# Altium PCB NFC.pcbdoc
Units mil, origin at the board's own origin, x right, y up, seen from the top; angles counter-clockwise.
Board outline 4070 x 3225 mil, 2 copper layers (Top Layer, Bottom Layer); 55 components, 46 nets, 197 pads, 132 vias.
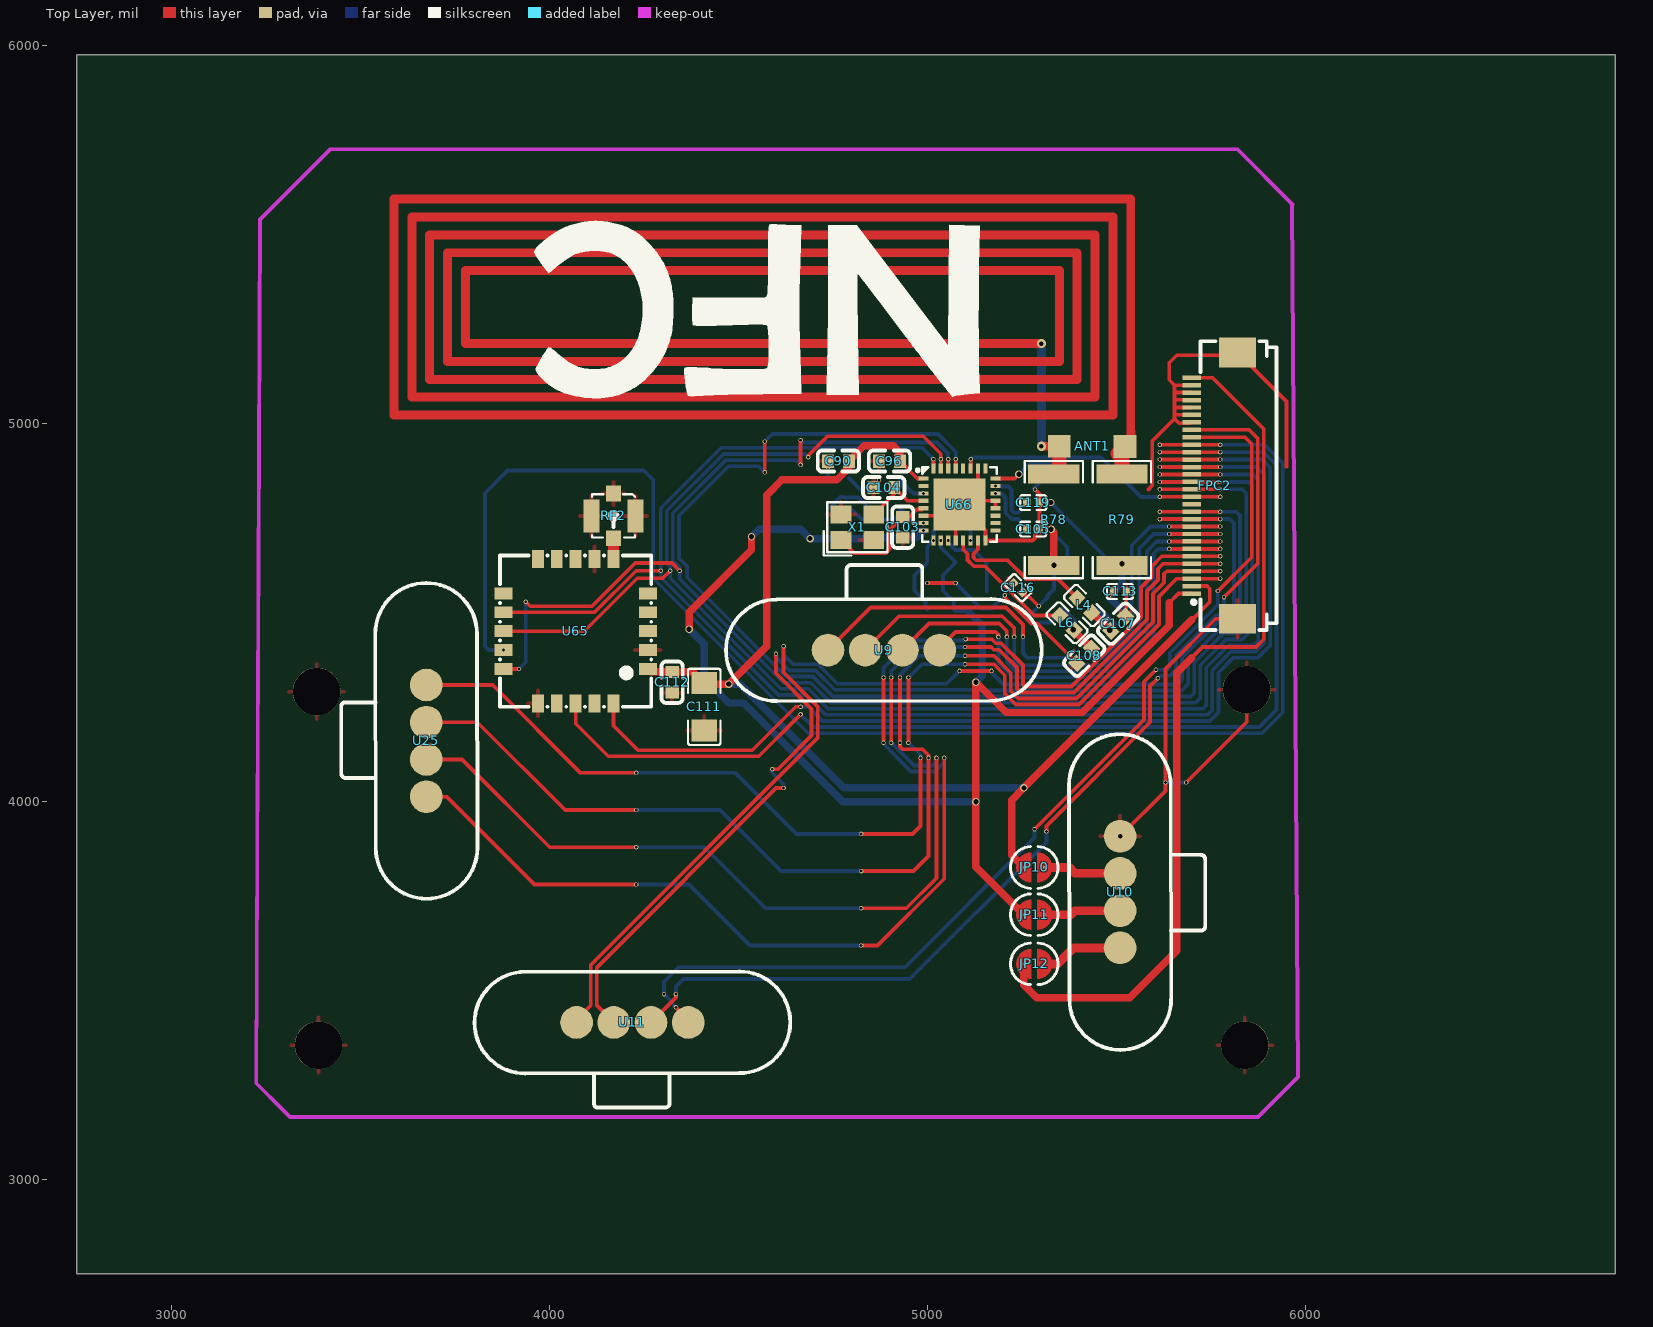
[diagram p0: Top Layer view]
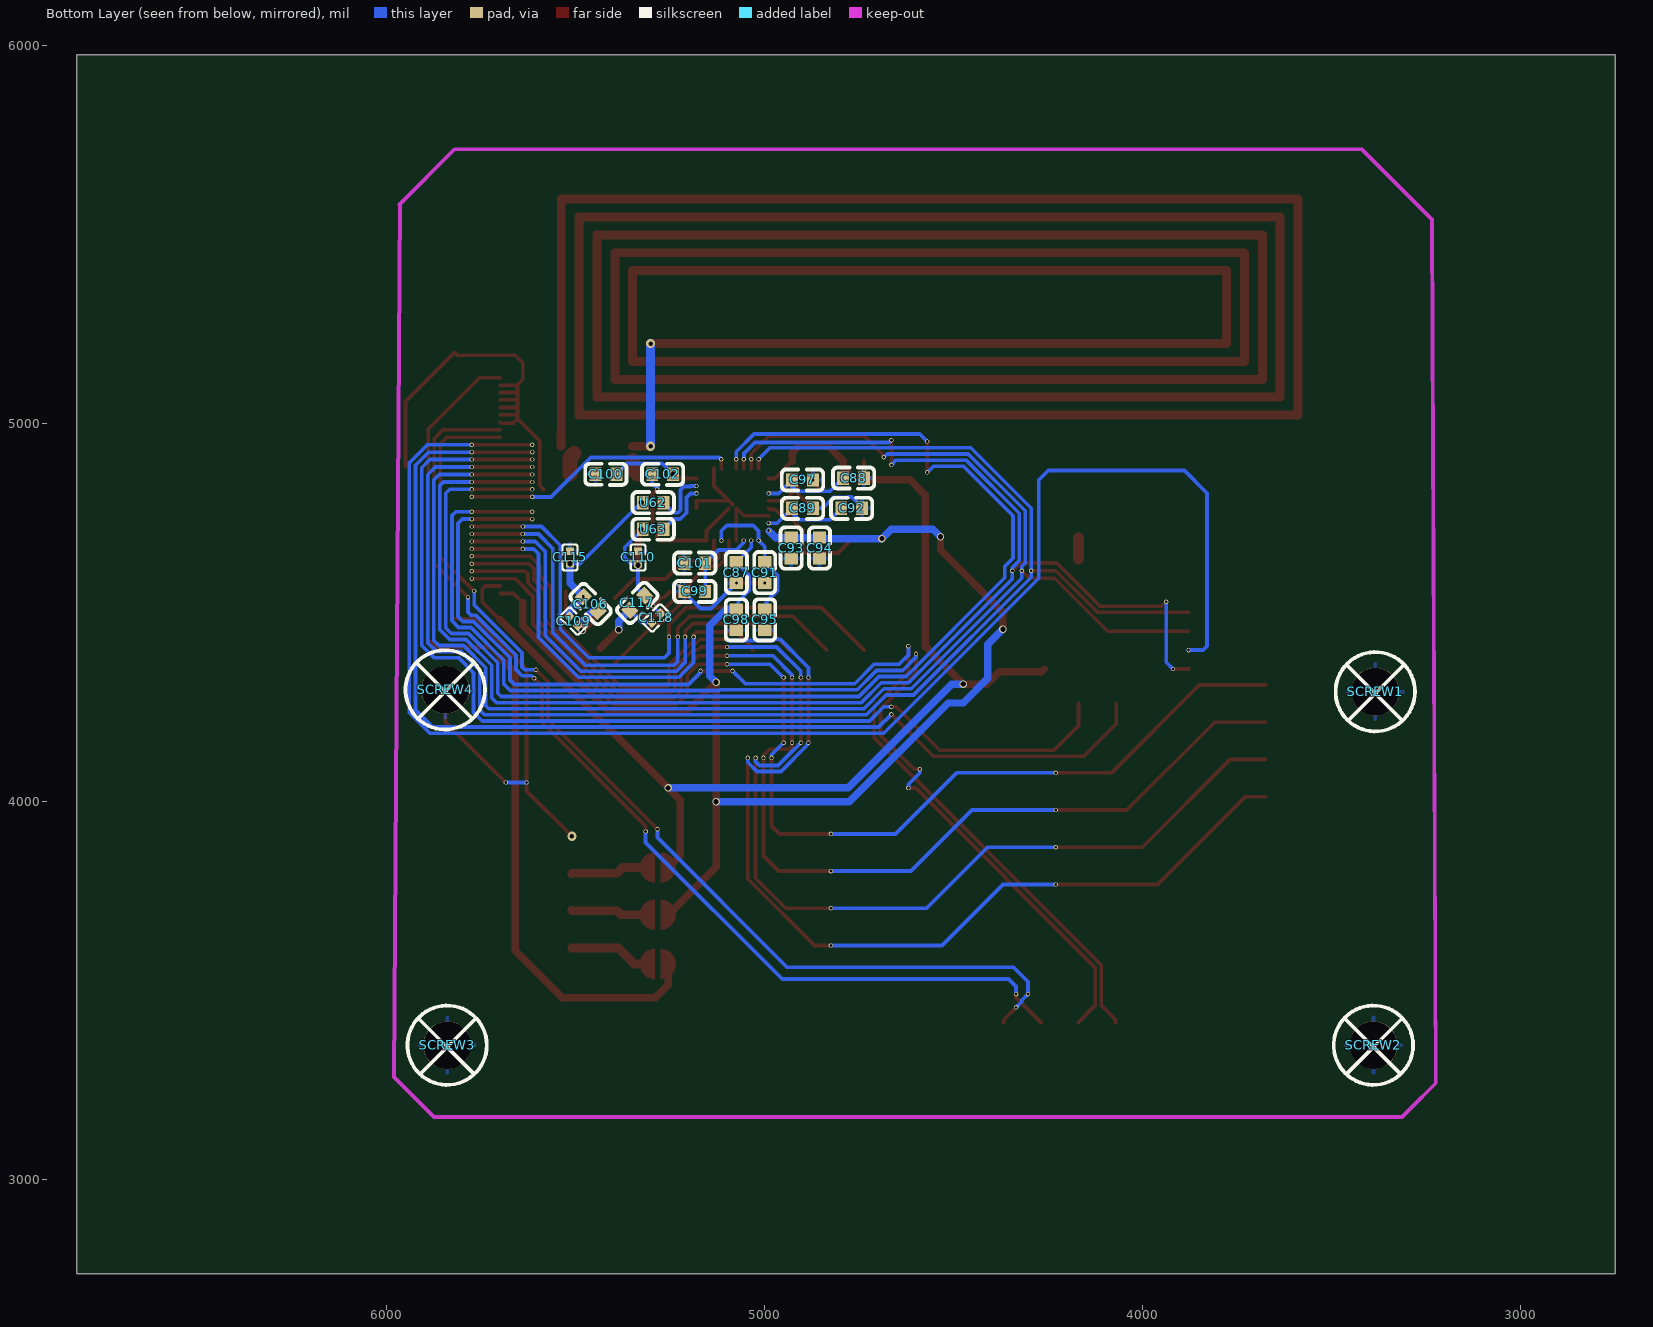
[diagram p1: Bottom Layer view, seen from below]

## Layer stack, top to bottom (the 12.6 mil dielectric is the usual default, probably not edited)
Top Layer: signal copper (thickness not stored)
Dielectric: dielectric 12.6, FR-4, Dk 4.8
Bottom Layer: signal copper (thickness not stored)

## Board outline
6820,2750 2750,2750 2750,5975 6820,5975

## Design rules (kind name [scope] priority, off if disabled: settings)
BoardOutlineClearance copperThickness1oz [All] p0: genericclearance=10 ignorepadtopadclearanceinfootprint=FALSE except(0: Arc-SplitContinuation Track-SplitContinuation SMDPad-SplitContinuation THPad-SplitContinuation Via-SplitContinuation Fill-SplitContinuation Poly-SplitContinuation Region-SplitContinuation Text-SplitContinuation; 6: Track-CutoutEdge SMDPad-CutoutEdge THPad-CutoutEdge Via-CutoutEdge Region-CutoutEdge; 11.8: Track-OutlineEdge SMDPad-OutlineEdge THPad-OutlineEdge Via-OutlineEdge Fill-OutlineEdge Region-OutlineEdge Poly-OutlineEdge Text-OutlineEdge Fill-CutoutEdge)
BoardOutlineClearance copperThickness2oz [All] p0: genericclearance=10 ignorepadtopadclearanceinfootprint=FALSE except(0: Arc-SplitContinuation Track-SplitContinuation SMDPad-SplitContinuation THPad-SplitContinuation Via-SplitContinuation Fill-SplitContinuation Poly-SplitContinuation Region-SplitContinuation Text-SplitContinuation; 6: Track-CutoutEdge SMDPad-CutoutEdge THPad-CutoutEdge Via-CutoutEdge Region-CutoutEdge; 11.8: Track-OutlineEdge SMDPad-OutlineEdge THPad-OutlineEdge Via-OutlineEdge Fill-OutlineEdge Region-OutlineEdge Poly-OutlineEdge Text-OutlineEdge Fill-CutoutEdge)
Clearance copperThickness1oz [(InNet('ESP_MISO') OR InNet('ESP_SCK') OR InNet('ESP_CS') OR InNet('ESP_MOSI') OR InNet('+5V') OR InNet('3V3_VDD') OR InNet('1V8_VDD') OR InNet('CS3') OR InNet('CS4') OR InNet('ESP_SDA') OR InNet('TXD0') OR InNet('RXD0') OR InNet('$3N153') OR InNet('CC_CSN') OR InNet('$3N151') OR InNet('ESP_SCL') OR InNet('NFC_IRQ') OR InNet('NFC_CS') OR InNet('CC_SCK') OR InNet('CC_MOSI') OR InNet('CC_MISO') OR InNet('CC_GDO2') OR InNet('CC_GDO0') OR InNet('$3N131') OR InNet('RFO2') OR InNet('RFO1') OR InNet('CS1') OR InNet('CS2') OR InNet('$3N159') OR InNet('$3N158') OR InNet('$3N160') OR InNet('$3N4436') OR InNet('$3N4438') OR InNet('$3N4437') OR InNet('RFI2') OR InNet('RFI1') OR InNet('$3N119') OR InNet('VDD_A') OR InNet('$3N123') OR InNet('AM') OR InNet('$3N154') OR InNet('GND') OR InNet('ANT1_1') OR InNet('XTO') OR InNet('XTI') OR InNet('$3N136'))] p1: gap=7 ignorepadtopadclearanceinfootprint=FALSE except(4: Track-Track; 6: Track-SMDPad SMDPad-SMDPad Track-THPad SMDPad-THPad THPad-THPad Track-Via SMDPad-Via THPad-Via Via-Via SMDPad-Fill THPad-Fill Via-Fill Fill-Fill Track-Region SMDPad-Region THPad-Region Via-Region Region-Region Track-Poly SMDPad-Poly THPad-Poly Via-Poly Fill-Poly Region-Poly Poly-Poly Track-Text SMDPad-Text THPad-Text Via-Text Fill-Text Region-Text Poly-Text Text-Text; 6.9: Track-Hole SMDPad-Hole THPad-Hole Via-Hole Fill-Hole Region-Hole Poly-Hole Text-Hole Sheet-Hole; 11.8: Track-Fill Fill-Region Track-Sheet SMDPad-Sheet THPad-Sheet Via-Sheet Fill-Sheet Region-Sheet Poly-Sheet Text-Sheet)
Clearance copperThickness2oz [All] p1: gap=7 ignorepadtopadclearanceinfootprint=FALSE except(6: Track-SMDPad SMDPad-SMDPad Track-THPad SMDPad-THPad THPad-THPad Track-Via SMDPad-Via THPad-Via Via-Via SMDPad-Fill THPad-Fill Via-Fill Fill-Fill Track-Region SMDPad-Region THPad-Region Via-Region Region-Region Track-Poly SMDPad-Poly THPad-Poly Via-Poly Fill-Poly Region-Poly Poly-Poly Track-Text SMDPad-Text THPad-Text Via-Text Fill-Text Region-Text Poly-Text Text-Text; 6.9: Track-Hole SMDPad-Hole THPad-Hole Via-Hole Fill-Hole Region-Hole Poly-Hole Text-Hole Sheet-Hole; 8: Track-Track; 11.8: Track-Fill Fill-Region Track-Sheet SMDPad-Sheet THPad-Sheet Via-Sheet Fill-Sheet Region-Sheet Poly-Sheet Text-Sheet)
DiffPairsRouting differentialPair [All] p1: maxuncoupledlength=10 minlimit=6 maxlimit=6 mostfreqgap=6 toplayer_minwidth=5 toplayer_prefwidth=10 toplayer_maxwidth=100 bottomlayer_minwidth=5 bottomlayer_prefwidth=10 bottomlayer_maxwidth=100
PasteMaskExpansion pasteMaskExpansion [All] p1: expansion=0
PlaneConnect innerPlane [All] p1: planeconnectstyle=Relief reliefexpansion=20 reliefentries=4 reliefconductorwidth=10 reliefairgap=10
PolygonConnect copperRegion [All] p1: connectstyle=Relief reliefentries=4 reliefconductorwidth=10 polygonreliefangle="90 Angle" airgapwidth=10
RoutingVias viaSize [All] p1: viastyle="Through Hole" holewidth=7.5 minholewidth=7.5 maxholewidth=248.0314 width=11.4 minwidth=11.4 maxwidth=300
SolderMaskExpansion solderMaskExpansion [All] p1: useseparateexpansions=TRUE expansion=2 expansionbottom=2
Width copperThickness1oz [All] p1: maxlimit=100 minlimit=5 preferedwidth=10
Width copperThickness2oz [All] p1: maxlimit=100 minlimit=8 preferedwidth=10

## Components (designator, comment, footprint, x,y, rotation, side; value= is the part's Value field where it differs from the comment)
ANT1 "NFC_13.56" "NFC ANTENNA" 5550,5010 r180 top
C87 "10nF" C0603 5075,4605 r90 bottom
C88 "2.2uF" C0603 4765,4855 r180 bottom
C89 "10nF" C0603 4900,4775 r180 bottom
C90 "2.2uF" C0603 4765,4900 r180 top
C91 "10nF" C0603 5000,4605 r90 bottom
C92 "2.2uF" C0603 4770,4775 r0 bottom
C93 "10nF" C0603 4930,4670 r90 bottom
C94 "2.2uF" C0603 4855,4670 r90 bottom
C95 "2.2uF" C0603 5000,4480 r90 bottom
C96 "10nF" C0603 4900,4900 r180 top
C97 "10nF" C0603 4900,4850 r180 bottom
C98 "2.2uF" C0603 5075,4480 r90 bottom
C99 "2.2uF" C0603 5185,4555 r180 bottom
C100 "1uF" C0603 5420,4865 r0 bottom
C101 "10nF" C0603 5185,4630 r180 bottom
C102 "10nF" C0603 5270,4865 r180 bottom
C103 "6pF" C0603 4935,4725 r90 top
C104 "6pF" C0603 4885,4830 r0 top
C105 "220pF" C0402 5280,4720 r0 top
C106 "82pF" C0603 5460.43,4521.89 r45 bottom
C107 "680pF" C0603 5505,4470 r45 top
C108 "680pF" C0603 5415,4385 r45 top
C109 "4pF" C0402 5505.43,4476.89 r225 bottom
C110 "110pF" C0402 5335,4645 r270 bottom
C111 "10uF" C1206 4410,4250 r90 top
C112 "100nF" C0603 4325,4315 r270 top
C113 "4pF" C0402 5510,4555 r0 top
C115 "110pF" C0402 5515,4645 r90 bottom
C116 "4pF" C0402 5240,4565 r315 top
C117 "82pF" C0603 5337.2,4524.96 r135 bottom
C118 "4pF" C0402 5287.2,4484.96 r315 bottom
C119 "220pF" C0402 5280,4790 r0 top
FPC2 "FPC-05F-30PH20" FPC-SMD_30P-P0.50_XUNPU_FPC-05F-30PH20 5760,4835 r90 top
JP10 "2P Solder UNBridge Jumper" "SOLDER BRIDGE 2P UNBRIDGED" 5285,3825 r180 top
JP11 "2P Solder UNBridge Jumper" "SOLDER BRIDGE 2P UNBRIDGED" 5285,3700 r180 top
JP12 "2P Solder UNBridge Jumper" "SOLDER BRIDGE 2P UNBRIDGED" 5285,3570 r180 top
L4 "270nH" L0603 5415.47,4518 r315 top
L6 "270nH" L0603 5369.51,4472.04 r315 top
R78 "2Ω" R2512 5335,4745 r90 top
R79 "2Ω" R2512 5515,4745 r90 top
RF2 "HC-RF-IPEX0303-01" IPEX-SMD_HC-RF-IPEX0303-01 4170,4755 r0 top
SCREW1 "Screw-M3" SCREW-M3 3385,4290 r180 bottom
SCREW2 "Screw-M3" SCREW-M3 3390,3355 r180 bottom
SCREW3 "Screw-M3" SCREW-M3 5840,3355 r180 bottom
SCREW4 "Screw-M3" SCREW-M3 5845,4295 r180 bottom
U9 "YZ92015035T-04025-01" CONN-SMD_4P-P2.50_YZ92015035T-04025-01 4885,4400 r180 top
U10 "YZ92015035T-04025-01" CONN-SMD_4P-P2.50_YZ92015035T-04025-01 5510,3760 r90 top
U11 "YZ92015035T-04025-01" CONN-SMD_4P-P2.50_YZ92015035T-04025-01 4220,3415 r0 top
U25 "YZ92015035T-04025-01" CONN-SMD_4P-P2.50_YZ92015035T-04025-01 3675,4160 r270 top
U62 "10pF" C0603 5295,4790 r0 bottom
U63 "10pF" C0603 5295,4719.65 r0 bottom
U65 "E07-400MM10S" COMM-SMD_E07-400MM10S 4070,4450 r180 top
U66 "ST25R3916B-AQWT" VFQFPN-32_L5.0-W5.0-P0.50-TL-EP3.5 5085,4785 r0 top
X1 "27.12MHz" CRYSTAL-SMD_4P-L3.2-W2.5-BL 4815,4725 r0 top

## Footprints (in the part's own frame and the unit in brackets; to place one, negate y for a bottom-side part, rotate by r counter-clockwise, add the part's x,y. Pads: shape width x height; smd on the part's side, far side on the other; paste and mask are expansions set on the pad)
C0402 [mm]
  rect 0.5x0.54 smd: 1(-0.42,0) 2(0.42,0)
  silkscreen extent -0.87,-0.5 0.87,0.5
C0603 [mm]
  rect 0.8x0.9 smd: 1(-0.7,0) 2(0.7,0)
  silkscreen extent -1.39,-0.71 1.39,0.71
C1206 [mm]
  rect 1.485x1.728 smd: 1(-1.593,0) 2(1.593,0)
  silkscreen extent -2.56,-1.09 2.56,1.09
COMM-SMD_E07-400MM10S [mm]
  rect 1.2x0.8 smd: 1(-4.85,2.54) 2(-4.85,1.27) 3(-4.85,0) 4(-4.85,-1.27) 5(-4.85,-2.54) 11(4.85,-2.54) 12(4.85,-1.27) 13(4.85,0) 14(4.85,1.27) 15(4.85,2.54)
  rect 0.8x1.2 smd: 6(-2.54,-4.85) 7(-1.27,-4.85) 8(0,-4.85) 9(1.27,-4.85) 10(2.54,-4.85) 16(2.54,4.85) 17(1.27,4.85) 18(0,4.85) 19(-1.27,4.85) 20(-2.54,4.85)
  silkscreen extent -5.08,-5.08 5.08,5.08
CONN-SMD_4P-P2.50_YZ92015035T-04025-01 [mm]
  round 2.2 smd: 1(-3.75,0) 2(-1.25,0) 3(1.25,0) 4(3.75,0)
  silkscreen extent -10.61,-5.72 10.61,3.43
CRYSTAL-SMD_4P-L3.2-W2.5-BL [mm]
  rect 1.4x1.2 smd: 1(-1.1,-0.85) 2(1.1,-0.85) 3(1.1,0.85) 4(-1.1,0.85)
  silkscreen extent -2.26,-1.91 2.03,1.68
FPC-SMD_30P-P0.50_XUNPU_FPC-05F-30PH20 [mm]
  rect 0.3x1.25 smd: 1(-7.25,1.537) 2(-6.75,1.537) 3(-6.25,1.537) 4(-5.75,1.537) 5(-5.25,1.537) 6(-4.75,1.537) 7(-4.25,1.537) 8(-3.75,1.537) 9(-3.25,1.537) 10(-2.75,1.537) 11(-2.25,1.537) 12(-1.75,1.537) 13(-1.25,1.537) 14(-0.75,1.537) 15(-0.25,1.537) 16(0.25,1.537) 17(0.75,1.537) 18(1.25,1.537) 19(1.75,1.537) 20(2.25,1.537) 21(2.75,1.537) 22(3.25,1.537) 23(3.75,1.537) 24(4.25,1.537) 25(4.75,1.537) 26(5.25,1.537) 27(5.75,1.537) 28(6.25,1.537) 29(6.75,1.537) 30(7.25,1.537)
  rect 2x2.5 smd: 31(8.94,-1.537) 32(-8.94,-1.537)
  silkscreen extent -9.7,-4.15 9.7,1.53
IPEX-SMD_HC-RF-IPEX0303-01 [mm]
  rect 1x1.05 smd: 1(0,-1.5) 4(0,1.5)
  rect 1.05x2.2 smd: 2(1.475,0) 3(-1.475,0)
  silkscreen extent -1.45,-1.45 1.45,1.45
L0603 [mm]
  rect 0.8x0.864 smd: 1(-0.7,0) 2(0.7,0)
  silkscreen extent -1.42,-0.65 1.42,0.65
"NFC ANTENNA" [mil]
  rect 60x60 smd: 1(27.16,71.65) 2(200.79,70.87)
  Top Layer lines w23.62: 248.03,70.87 245.27,70.87 200.79,70.87 ; 248.03,-200.79 1771.66,-200.79 1771.66,-393.7 200.79,-393.7 200.79,-153.54 1818.9,-153.54 1818.9,-440.94 153.54,-440.94 153.54,-106.3 1866.14,-106.3 1866.14,-488.19 106.3,-488.19 106.3,-59.06 1913.38,-59.06 1913.38,-535.43 59.1,-535.4 59.1,-11.8 ; 59.06,-11.81 1960.63,-11.81 1960.63,-582.68 11.81,-582.68 11.81,-11.81 11.42,70.87
  Bottom Layer lines w23.62: 248.03,70.87 248.03,-200.79
  silkscreen extent 411,-525 1590,-56
R2512 [mil]
  rect 50.49x136.06 smd: 1(-120.72,0) 2(120.72,0)
  silkscreen extent -155,-77 155,77
SCREW-M3 [mil]
  round 126 hole 126: 1(0,0)
  silkscreen extent -105,-105 105,105
"SOLDER BRIDGE 2P UNBRIDGED" [mm]
  round 0.2 smd: 1(-0.65,0) 2(0.75,0)
  Top Layer region: 0.25,-1 0.296,-0.999 0.342,-0.996 0.388,-0.99 0.434,-0.983 0.479,-0.973 0.524,-0.962 0.568,-0.948 0.611,-0.932 0.654,-0.915 0.696,-0.895 0.737,-0.874 0.776,-0.85 0.815,-0.825 0.853,-0.798 0.889,-0.769 0.924,-0.739 0.957,-0.707 0.989,-0.674 1.019,-0.639 1.048,-0.603 1.075,-0.565 1.1,-0.526 1.124,-0.487 1.145,-0.446 1.165,-0.404 1.182,-0.361 1.198,-0.318 1.212,-0.274 1.223,-0.229 1.233,-0.184 1.24,-0.138 1.246,-0.092 1.249,-0.046 1.25,0 1.249,0.046 1.246,0.092 1.24,0.138 1.233,0.184 1.223,0.229 1.212,0.274 1.198,0.318 1.182,0.361 1.165,0.404 1.145,0.446 1.124,0.487 1.1,0.526 1.075,0.565 1.048,0.603 1.019,0.639 0.989,0.674 0.957,0.707 0.924,0.739 0.889,0.769 0.853,0.798 0.815,0.825 0.776,0.85 0.737,0.874 0.696,0.895 0.654,0.915 0.611,0.932 0.568,0.948 0.524,0.962 0.479,0.973 0.434,0.983 0.388,0.99 0.342,0.996 0.296,0.999 0.25,1
  Top Layer region: -0.15,-1 -0.196,-0.999 -0.242,-0.996 -0.288,-0.99 -0.334,-0.983 -0.379,-0.973 -0.424,-0.962 -0.468,-0.948 -0.511,-0.932 -0.554,-0.915 -0.596,-0.895 -0.637,-0.874 -0.676,-0.85 -0.715,-0.825 -0.753,-0.798 -0.789,-0.769 -0.824,-0.739 -0.857,-0.707 -0.889,-0.674 -0.919,-0.639 -0.948,-0.603 -0.975,-0.565 -1,-0.526 -1.024,-0.487 -1.045,-0.446 -1.065,-0.404 -1.082,-0.361 -1.098,-0.318 -1.112,-0.274 -1.123,-0.229 -1.133,-0.184 -1.14,-0.138 -1.146,-0.092 -1.149,-0.046 -1.15,0 -1.149,0.046 -1.146,0.092 -1.14,0.138 -1.133,0.184 -1.123,0.229 -1.112,0.274 -1.098,0.318 -1.082,0.361 -1.065,0.404 -1.045,0.446 -1.024,0.487 -1,0.526 -0.975,0.565 -0.948,0.603 -0.919,0.639 -0.889,0.674 -0.857,0.707 -0.824,0.739 -0.789,0.769 -0.753,0.798 -0.715,0.825 -0.676,0.85 -0.637,0.874 -0.596,0.895 -0.554,0.915 -0.511,0.932 -0.468,0.948 -0.424,0.962 -0.379,0.973 -0.334,0.983 -0.288,0.99 -0.242,0.996 -0.196,0.999 -0.15,1
  silkscreen extent -1.55,-1.4 1.65,1.4
VFQFPN-32_L5.0-W5.0-P0.50-TL-EP3.5 [mm]
  rect 0.665x0.28 smd: 1(-2.42,1.75) 2(-2.42,1.25) 3(-2.42,0.75) 4(-2.42,0.25) 5(-2.42,-0.25) 6(-2.42,-0.75) 7(-2.42,-1.25) 8(-2.42,-1.75) 17(2.42,-1.75) 18(2.42,-1.25) 19(2.42,-0.75) 20(2.42,-0.25) 21(2.42,0.25) 22(2.42,0.75) 23(2.42,1.25) 24(2.42,1.75)
  rect 0.28x0.665 smd: 9(-1.75,-2.42) 10(-1.249,-2.42) 11(-0.75,-2.42) 12(-0.249,-2.42) 13(0.25,-2.42) 14(0.751,-2.42) 15(1.25,-2.42) 16(1.751,-2.42) 25(1.751,2.42) 26(1.25,2.42) 27(0.751,2.42) 28(0.25,2.42) 29(-0.249,2.42) 30(-0.75,2.42) 31(-1.249,2.42) 32(-1.75,2.42)
  rect 3.5x3.5 smd: 33(0,0)
  silkscreen extent -2.9,-2.5 2.5,2.5

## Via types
v1: diameter 11.42, hole 7.48, Top Layer to Bottom Layer, 102 vias
v2: diameter 19.68, hole 13.78, Top Layer to Bottom Layer, 14 vias
v3: diameter 11.4, hole 7.5, Top Layer to Bottom Layer, 13 vias
v4: diameter 24, hole 12, Top Layer to Bottom Layer, 2 vias
v5: diameter 24.41, hole 12.2, Top Layer to Bottom Layer, 1 vias

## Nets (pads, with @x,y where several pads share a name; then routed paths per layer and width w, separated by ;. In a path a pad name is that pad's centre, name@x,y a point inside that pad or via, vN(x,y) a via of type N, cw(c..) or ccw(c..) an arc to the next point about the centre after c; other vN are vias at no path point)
1V8_VDD: FPC2.30 JP12.2 | length 2330.7
  Top Layer w10: FPC2.30 5754.57,5120.43 5890,4985 5890,4428.79 5869.14,4407.93 5727.93,4407.93 5700,4380
  Top Layer w19.68: JP12.2 5255.47,3514.53 5290,3480 5535,3480 5660,3605 5660,4340 5700,4380
3V3_VDD: C90.1 C96.1 C111.2 C112.1 FPC2.2 JP10.2 U65.1 U66.1 | length 3212
  Top Layer w10: C96.1 4973.66,4853.9 U66.1 ; FPC2.2 5740,4569.25 5747.07,4562.18 5747.07,4527.07 5700,4480
  Top Layer w19.68: U65.1 4268.37,4342.56 C112.1 4380.14,4342.56 C111.2 4412.7,4310 v2(4475,4310) 4575,4410 4575,4810 4615,4850 4760,4850 4792.56,4882.56 C90.1 4832.56,4940 4910,4940 4927.56,4922.44 C96.1 ; JP10.2 5223.12,3857.35 5223.12,4003.12 v2(5255.47,4035.47) 5700,4480
  Bottom Layer w19.68: v2(4475,4310) 4505,4310 4779.53,4035.47 v2(5255.47,4035.47)
$3N119: C88.1 C97.1 U66.3 | length 249
  Bottom Layer w10: C88.1 4827.56,4820 4915,4820 4927.56,4832.56 C97.1 4963.04,4814.52 v1(4989.73,4814.52)
$3N123: C91.2 C95.2 U66.9 U66.14 | length 378.3
  Bottom Layer w10: C95.2 4995,4512.56 4995,4528.44 4966.3,4557.14 4966.3,4597.74 4995,4626.44 4995,4627.56 C91.2 5000,4673.61 v1(5016.12,4689.72) 5016.12,4715 5030.56,4729.44 5100.56,4729.44 5115,4715 5115,4690.17 v1(5114.55,4689.72)
$3N131: C100.1 C102.2 U66.24 | length 240.5
  Top Layer w10: U66.24 5231.33,4853.89 v2(5242.44,4865)
  Bottom Layer w10: v2(5242.44,4865) 5271.14,4893.7 5363.74,4893.7 C100.1
$3N136: RF2.1 U65.6 | length 55
  Top Layer w30: U65.6 RF2.1
$3N151: C106.1 C107.1 C109.2 L4.2 | length 152
  Top Layer w19.68: L4.2 5436.94,4498.52 v2(5482.73,4452.73)
  Bottom Layer w19.68: C106.1 5456.53,4502.4 C109.2 5493.73,4463.73 v2(5482.73,4452.73)
$3N153: C108.2 C117.1 C118.2 L6.2 | length 204.3
  Top Layer w19.68: v2(5385.93,4453.72) 5385.93,4453.05 C108.2
  Bottom Layer w10: C118.2 5324.48,4473.27 C117.1
  Bottom Layer w19.68: C117.1 5385.93,4476.23 v2(5385.93,4453.72)
$3N154: C106.2 C109.1 C113.1 C115.1 R79.1 U62.2 | length 444.5
  Top Layer w10: v3(5479.92,4541.38) C113.1@5493.46,4554.92
  Bottom Layer w10: v2(5326.49,4790.35) 5488.39,4628.46 v2(5515,4628.46)
  Bottom Layer w19.68: v2(5515,4628.46) 5515,4576.46 v3(5479.92,4541.38) 5517.12,4504.17 C109.1
$3N158: ANT1.1 R79.2 | length 58.7
  Top Layer w39.37: ANT1.1@5504.6,4920.11 5515,4909.71 R79.2
$3N159: ANT1.2 R78.2 | length 41.8
  Top Layer w39.37: R78.2 5349.21,4879.93 5349.21,4901.65
$3N160: C110.2 C116.2 C117.2 C118.1 R78.1 U63.2 | length 449.8
  Top Layer w10: C116.2 5265,4540 5271.23,4540 v3(5295.04,4516.19)
  Top Layer w19.68: v2(5327.56,4719.65) 5335,4712.21 v2(5335,4624.28)
  Bottom Layer w10: C118.1 v3(5295.04,4516.19) 5317.71,4538.86 C117.2 5335,4561.74 C110.2 5353.46,4628.46 5370,4645 5370,4672.21 U63.2
$3N4436: JP12.1 U10.1 | length 217
  Top Layer w23.62: JP12.1 5345,3570 5387.4,3612.4 U10.1
$3N4437: JP11.1 U10.2 | length 203.5
  Top Layer w23.62: JP11.1 5380,3700 5390,3710 U10.2
$3N4438: JP10.1 U10.3 | length 205.6
  Top Layer w23.62: JP10.1 5375,3825 5390,3810 U10.3
+5V: C87.2 C93.2 C94.2 C98.2 FPC2.1 JP11.2 U66.8 U66.10 | length 3700.9
  Top Layer w10: 5640,4525 5664.57,4549.57 FPC2.1
  Top Layer w19.68: v2(4370,4455) 4370,4500 4535,4665 v2(4535,4700) ; JP11.2 5128.58,3826.89 v2(5128.58,3998.69) v2(5128.58,4315) 5128.83,4315 5208.83,4235 5410,4235 5640,4465 5640,4525
  Bottom Layer w10: v1(5035.81,4689.72) 5035.81,4671.75 C87.2 5070,4627.56 5070,4626.44 5041.3,4597.74 5041.3,4557.14 5070,4528.44 5070,4512.56 C98.2
  Bottom Layer w19.68: v2(4370,4455) 4410,4415 4410,4325 4475,4260 4515,4260 4776.31,3998.69 v2(5128.58,3998.69) ; v2(4535,4700) 4555,4720 4665,4720 v2(4690,4695) 4852.44,4695 C94.2 C93.2 4971.2,4697.56 v1@4987.88,4714.24 ; C98.2 5102.44,4507.56 5145,4465 5145,4331.42 v2(5128.58,4315)
  other v1: 4989.73,4716.09
AM: C99.2 C101.2 U66.11 | length 204.7
  Bottom Layer w10: v1(5055.49,4689.72) 5055.49,4684.51 5075,4665 5122.44,4665 C101.2 C99.2
ANT1_1: 
  other v4: 5301.97,4939.13 5301.97,5210.79
CC_CSN: FPC2.21 U65.14 | length 4061
  Top Layer w10: v1(5615,4943.27) FPC2.21 v1(5775,4943.27)
  Bottom Layer w10: v1@3879.05,4400 3840,4400 3830,4410 3830,4815 3890,4875 4250,4875 4275,4850 4275,4590 4685,4180 5885,4180 5940,4235 5940,4895 5891.73,4943.27 v1(5775,4943.27)
  other v1: 3879.06,4399.99
CC_GDO0: FPC2.20 U65.18 | length 2992.5
  Top Layer w10: U65.18 4070,4205 4155.98,4119.02 4554.02,4119.02 v1(4665,4230) ; v1(5615,4923.58) FPC2.20 v1(5775,4923.58)
  Bottom Layer w10: v1(4665,4230) 4698.7,4196.3 5878.7,4196.3 5923.7,4241.3 5923.7,4888.7 5888.81,4923.58 v1(5775,4923.58)
CC_GDO2: FPC2.19 U65.20 | length 2802.3
  Top Layer w10: U65.20 4170,4200 4235,4135 4537.16,4135 4652.16,4250 v1(4665,4250) ; v1(5615,4903.9) FPC2.19 v1(5775,4903.9)
  Bottom Layer w10: v1(4665,4250) 4685,4250 4722.71,4212.29 5747.29,4212.29 5770,4235 5770,4340 5810,4380 5875,4380 5907.39,4412.39 5907.39,4882.39 5885.89,4903.9 v1(5775,4903.9)
CC_MISO: FPC2.18 U65.12 U66.32 | length 4085.4
  Top Layer w10: U65.12 4119.99,4499.99 4230,4610 v1(4295,4610) ; U66.32 v1(5016.12,4905) ; v1(5615,4884.21) FPC2.18 v1(5775,4884.21)
  Bottom Layer w10: v1(5016.12,4905) 4986.12,4935 4455,4935 4295,4775 v1(4295,4610) 4295,4592.61 4606.3,4281.3 4678.7,4281.3 4731.2,4228.8 5741.2,4228.8 5754.02,4241.62 5754.02,4346.62 5803.38,4395.98 5868.38,4395.98 5891.41,4419.02 5891.41,4863.59 5870.79,4884.21 v1(5775,4884.21)
CC_MOSI: FPC2.17 U65.13 U66.31 | length 4087.1
  Top Layer w10: U65.13 4092.6,4449.99 4232.61,4590 4300,4590 v1(4320,4610) ; v1(4685,4910) 4685,4915 4735.83,4965.83 4989.17,4965.83 5035.81,4919.19 v1(5035.81,4905) U66.31 ; v1(5615,4864.53) FPC2.17 v1(5775,4864.53)
  Bottom Layer w10: v1(4685,4910) 4675.98,4919.02 4461.62,4919.02 4310.98,4768.38 4310.98,4630 4320,4620.98 v1(4320,4610) 4320,4590.21 4612.61,4297.61 4685,4297.61 4737.61,4245 5730,4245 5738.03,4253.03 5738.03,4353.24 5796.76,4411.97 5861.76,4411.97 5875.43,4425.64 5875.43,4850 5860.9,4864.53 v1(5775,4864.53)
CC_SCK: FPC2.16 U65.15 U66.30 | length 4195.6
  Top Layer w10: U65.15 v1(3920,4350) ; v1(3937.99,4527.99) 3950,4515.97 4113.37,4515.97 4227.39,4630 4325,4630 v1(4345,4610) ; v1(4665,4890) v1(4665,4955) ; U66.30 v1(5055.49,4905) ; v1(5615,4844.84) FPC2.16 v1(5775,4844.84)
  Bottom Layer w10: v1(3920,4350) 3937.99,4367.99 v1(3937.99,4527.99) ; v1(4665,4890) 4652.61,4902.39 4467.61,4902.39 4326.97,4761.76 4326.97,4636.62 4345,4618.59 v1(4345,4610) 4345,4588.59 4620,4313.59 4691.62,4313.59 4744.23,4260.98 5710,4260.98 5722.05,4273.03 5722.05,4359.86 5790.14,4427.95 5832.95,4427.95 5859.44,4454.44 5859.44,4835 5849.6,4844.84 v1(5775,4844.84) ; v1(4665,4955) 4670.98,4949.02 5025.98,4949.02 5055,4920 5055,4905.49 v1(5055.49,4905)
CS1: FPC2.7 U9.1 | length 1128.3
  Top Layer w10: U9.1 5032.64,4405.42 5075,4447.78 5180.96,4447.78 5188.03,4440.71 v1(5188.03,4435) ; v1(5640,4667.68) FPC2.7 v1(5775,4667.68)
  Bottom Layer w10: v1(5188.03,4435) 5188.03,4366.74 5226.76,4328.01 5492.25,4328.01 5598.31,4434.07 5598.31,4654.9 5611.08,4667.68 v1(5640,4667.68)
CS2: FPC2.8 U9.2 | length 1243.1
  Top Layer w10: U9.2 5004.38,4470.18 5190.24,4470.18 5210.43,4449.99 v1(5210.43,4435) ; v1(5640,4687.36) FPC2.8 v1(5775,4687.36)
  Bottom Layer w10: v1(5210.43,4435) 5210.43,4366.94 5233.38,4344 5485.63,4344 5580.32,4438.69 5580.32,4660.83 5606.85,4687.36 v1(5640,4687.36)
CS3: FPC2.9 U9.3 | length 1355.6
  Top Layer w10: U9.3 4925.54,4489.75 5198.34,4489.75 5230,4458.09 v1(5230,4435) ; v1(5640,4707.05) FPC2.9 v1(5775,4707.05)
  Bottom Layer w10: v1(5230,4435) 5230,4369.98 5240,4359.98 5473.76,4359.98 5560.63,4446.85 5560.63,4668.99 5598.69,4707.05 v1(5640,4707.05)
CS4: FPC2.10 U9.4 | length 1459.2
  Top Layer w10: U9.4 4850.22,4512.86 5207.92,4512.86 5253.11,4467.67 v1(5253.11,4435) ; v1(5640,4726.73) FPC2.10 v1(5775,4726.73)
  Bottom Layer w10: v1(5253.11,4435) 5253.11,4391.89 5265.34,4379.66 5465.61,4379.66 5540.95,4455 5540.95,4481.85 5542.59,4483.48 5542.59,4492.58 5540.95,4494.22 5540.95,4677.14 5590.54,4726.73 v1(5640,4726.73)
ESP_CS: FPC2.6 U25.4 | length 3551.9
  Top Layer w10: U25.4 3728.31,4012.36 3960.67,3780 v1(4230,3780) ; v1(4825,3618.51) 4868.51,3618.51 5045,3795 v1(5045,4115) ; v1(4884.25,4155) v1(4884.25,4327.64) ; v1(5101.51,4428.95) 5170.48,4428.95 5181.12,4418.31 5195.22,4418.31 5252.95,4360.57 5252.95,4308.3 5257.47,4303.78 5381.51,4303.78 5565,4487.27 5565,4565.47 5594.02,4594.48 5594.02,4621.62 5620.38,4647.99 FPC2.6 v1(5775,4647.99)
  Bottom Layer w10: v1(4230,3780) 4370,3780 4531.49,3618.51 v1(4825,3618.51) ; v1(4884.25,4155) 4887.76,4151.5 4887.76,4148.09 4956.83,4079.02 5020.55,4079.02 5045,4103.46 v1(5045,4115) ; v1(4884.25,4327.64) 4884.25,4353.22 4959.98,4428.95 4974.5,4428.95 4977.73,4425.71 5097.27,4425.71 5100.5,4428.95 v1(5101.51,4428.95)
ESP_MISO: FPC2.4 U25.2 | length 3189.4
  Top Layer w10: U25.2 3809.84,4209.2 4042.2,3976.84 v1(4230,3976.84) ; v1(4825,3815.35) 4963.39,3815.35 5003.03,3855 v1(5003.03,4115) 5003.03,4121.97 4987.07,4137.93 4934.67,4137.93 4927.6,4145 v1(4927.6,4155) v1(4927.6,4327.64) ; v1(5100,4384.9) 5176.31,4384.9 5220.98,4340.23 5220.98,4291.62 5240.79,4271.81 5394.75,4271.81 5596.97,4474.03 5596.97,4548.92 5625.98,4577.94 5625.98,4600.98 5633.62,4608.62 FPC2.4 v1(5775,4608.62)
  Bottom Layer w10: v1(4230,3976.84) 4451.53,3976.84 4613.02,3815.35 v1(4825,3815.35) ; v1(4927.6,4327.64) 4927.6,4334.28 4978.22,4384.9 v1(5100,4384.9)
ESP_MOSI: FPC2.3 U25.1 | length 2978.8
  Top Layer w10: U25.1 3850.62,4307.64 4082.98,4075.28 v1(4230,4075.28) ; v1(4825,3913.79) 4960.84,3913.79 4982.05,3935 v1(4982.05,4115) ; v1(4950,4155) v1(4950,4327.64) ; v1(5100,4362.5) 5176.11,4362.5 5205,4333.61 5205,4285 5234.17,4255.83 5401.37,4255.83 5612.95,4467.41 5612.95,4542.17 5659.72,4588.94 FPC2.3 v1(5775,4588.94)
  Bottom Layer w10: v1(4230,4075.28) 4492.31,4075.28 4653.79,3913.79 v1(4825,3913.79) ; v1(4950,4155) 4982.05,4122.95 v1(4982.05,4115) ; v1(4950,4327.64) 4951.1,4327.64 4985.96,4362.5 v1(5100,4362.5)
ESP_SCK: FPC2.5 U25.3 | length 3393.5
  Top Layer w10: U25.3 3769.08,4110.79 4001.44,3878.43 v1(4230,3878.43) ; v1(4825,3716.94) 4944.34,3716.94 5024.02,3796.62 v1(5024.02,4115) ; v1(4904.45,4155) v1(4904.45,4327.64) ; v1(5100,4408.05) 5168.77,4408.05 5175.93,4400.89 5190.08,4400.89 5236.97,4353.99 5236.97,4298.24 5247.41,4287.8 5388.13,4287.8 5580.98,4480.65 5580.98,4556.43 5610,4585.45 5610,4615 5623.31,4628.31 FPC2.5 v1(5775,4628.31)
  Bottom Layer w10: v1(4230,3878.43) 4410.77,3878.43 4572.26,3716.94 v1(4825,3716.94) ; v1(4904.45,4155) 4910.91,4148.54 4910.91,4148.09 4920.68,4138.31 4921.14,4138.31 4964.45,4095 5013.93,4095 5024.02,4105.08 v1(5024.02,4115) ; v1(4904.45,4327.64) 4904.45,4343.87 4968.63,4408.05 v1(5100,4408.05)
ESP_SCL: FPC2.12 U11.2 | length 3194.4
  Top Layer w10: U11.2 4125.98,3459.82 4125.98,3560.77 4600.21,4035 v1(4620,4035) ; v1(4590,4085) 4605,4085 4694.02,4174.02 4694.02,4244.59 4600,4338.61 v1(4600,4390) ; v1(5615,4766.1) FPC2.12 v1(5775,4766.1)
  Bottom Layer w10: v1(4590,4085) 4590,4075 4620,4045 v1(4620,4035) ; v1(4600,4390) 4600,4381.37 4635,4346.37 4704.05,4346.37 4755.46,4294.96 5119.16,4294.96 5121.17,4292.95 5673.03,4292.95 5690.08,4310 5690.08,4373.1 5776.9,4459.92 5810,4459.92 5827.47,4477.39 5827.47,4756.1 5817.47,4766.1 v1(5775,4766.1)
ESP_SDA: FPC2.11 U11.1 | length 3129.8
  Top Layer w10: U11.1 4072.36,3422.36 4110,3460 4110,3567.39 4710,4167.39 4710,4251.21 4620,4341.21 v1(4620,4410) ; v1(5085,4345) v1(5170,4345) ; v1(5615,4746.42) FPC2.11 v1(5775,4746.42)
  Bottom Layer w10: v1(4620,4410) 4620,4387.35 4645,4362.35 4710.67,4362.35 4762.08,4310.94 5050.94,4310.94 v1(5085,4345) ; v1(5170,4345) 5170,4340.94 5202.01,4308.94 5661.73,4308.94 5674.09,4321.3 5674.09,4379.73 5770.27,4475.91 5798.74,4475.91 5811.49,4488.66 5811.49,4735 5800.07,4746.42 v1(5775,4746.42)
GND: C87.1 C88.2 C89.2 C90.2 C91.1 C92.1 C93.1 C94.1 C95.1 C96.2 C97.2 C98.1 C99.1 C100.2 C101.1 C102.1 C103.1 C104.1 C105.2 C107.2 C108.1 C110.1 C111.1 C112.2 C113.2 C115.2 C116.1 C119.2 FPC2.24 FPC2.25 FPC2.26 FPC2.27 FPC2.28 FPC2.29 FPC2.31 FPC2.32 RF2.2 RF2.3 RF2.4 SCREW1.1 SCREW2.1 SCREW3.1 SCREW4.1 U10.4 U65.2 U65.7 U65.16 U66.6 U66.12 U66.16 U66.20 U66.21 U66.26 U66.33 X1.2 X1.4 | length 3961.8
  Top Layer w10: v3(4737.44,4877.64) C90.2 ; C104.1 4872.44,4845 v3(4872.44,4850) ; U66.6 5055.47,4755.47 5075.18,4775.18 U66.12 ; v3(5000,4577.44) v3(5075,4577.44) ; U66.33 U66.33@5094.83,4794.83 ; U66.33@5094.85,4775.15 5153.92,4716.08 U66.16 5277.93,4689.73 5285,4696.8 5285,4708.46 C105.2 C119.2 5296.54,4813.46 v3(5285,4825) ; U66.26 5134.23,4834.23 U66.33@5094.83,4794.83 ; U66.20 U66.21 U66.33@5094.83,4794.83 ; v3(5205,4545) 5205,4540 5275,4470 5291.02,4470 C108.1 ; v5(5510,3907.64) 5630,4027.64 v3(5630,4050) 5630,4350 5763.04,4483.04 FPC2.32 ; C107.2 5526.54,4491.54 C113.2 ; 5585,4825 5595,4835 5595,4952.72 5654.25,5011.97 ; v3(5685,4050) 5845,4210 SCREW4.1 ; FPC2.24 5697.15,5000 5666.22,5000 5654.25,5011.97 ; FPC2.25 5698.97,5022.51 5654.25,5022.51 ; FPC2.26 5699.26,5041.48 5654.25,5041.48 ; FPC2.27 5698.88,5061.97 5654.25,5061.97 ; FPC2.28 5655.6,5081.06 5654.25,5079.71 ; FPC2.29 5654.25,5100.75 ; 5950,4885 5950,5057.5 FPC2.31 5813.56,5180 5660,5180 5640,5160 5640,5115 5654.25,5100.75 ; 5654.25,5011.97 5654.25,5022.51 ; 5654.25,5022.51 5654.25,5041.48 ; 5654.25,5041.48 5654.25,5061.97 ; 5654.25,5061.97 5654.25,5079.71 ; 5654.25,5079.71 5654.25,5100.75
  Bottom Layer w10: C88.2 v3(4737.44,4877.64) ; C92.1 4742.44,4777.44 4770,4805 4780,4805 4781.3,4803.7 4817.86,4803.7 4846.56,4775 C89.2 ; v3(5075,4577.44) 5142.44,4510 5170,4510 v3(5205,4545) ; C99.1 5228.3,4570.74 v3(5228.3,4576.7) ; v3@5282.5,4827.5 5297.56,4842.56 C102.1 ; v3(5630,4050) v3(5685,4050)
NFC_CS: FPC2.15 U66.29 | length 3440.1
  Top Layer w10: v1(4570,4870) v1(4570,4951.69) ; U66.29 v1(5075.18,4905) ; v1(5615,4825.16) FPC2.15 v1(5775,4825.16)
  Bottom Layer w10: v1(4570,4870) 4553.91,4886.09 4473.91,4886.09 4343.1,4755.28 4343.1,4643.1 4365,4621.19 4365,4591.19 4625.81,4330.38 4697.43,4330.38 4750.85,4276.97 5696.97,4276.97 5706.06,4286.06 5706.06,4366.48 5783.52,4443.94 5828.94,4443.94 5843.46,4458.46 5843.46,4815 5833.3,4825.16 v1(5775,4825.16) ; v1(4570,4951.69) 4590,4971.69 5028.31,4971.69 5075.18,4924.82 v1(5075.18,4905)
NFC_IRQ: FPC2.14 U66.27 | length 730.4
  Top Layer w10: U66.27 5115,4880.73 v1(5115,4905) ; v1(5615,4805.47) FPC2.14 v1(5775,4805.47)
  Bottom Layer w10: v1(5115,4905) 5119.69,4909.69 5460.31,4909.69 5565,4805 5614.53,4805 v1(5615,4805.47)
RFI1: C105.1 U63.1 U66.22 | length 149.9
  Bottom Layer w10: v1(5180.28,4814.52) 5195.98,4814.52 5207.01,4803.5 5207.01,4763.44 5223.45,4747 5240.08,4747 v3(5267.44,4719.65)
RFI2: C119.1 U62.1 U66.23 | length 159.5
  Bottom Layer w10: v1(5180.28,4834.2) 5195.99,4834.2 5197.83,4832.36 5214.45,4832.36 5223.01,4823.81 5223.01,4770.07 5230.08,4763 5240.08,4763 v3(5267.44,4790.35)
RFO1: L6.1 U66.13 | length 360.5
  Top Layer w10: U66.13 5094.86,4666.63 5106.55,4654.94 5106.55,4638.32 5122.99,4621.87 5152.56,4621.87 5282.9,4491.53 L6.1
RFO2: L4.1 U66.15 | length 367.6
  Top Layer w10: U66.15 5134.23,4666.63 5122.55,4654.94 5122.55,4644.94 5129.62,4637.87 5212.59,4637.87 5262.42,4588.05 5345.43,4588.05 L4.1
RXD0: FPC2.22 U11.4 | length 2734.6
  Top Layer w10: v1(4335,3455) 4367.64,3422.36 U11.4 ; v1(5283.7,3926.3) 5573.19,4215.79 5573.19,4316.22 v1(5605,4348.03) ; FPC2.22 5840.08,4962.95 5858.03,4945 5858.03,4645.64 v1(5768.7,4556.3)
  Bottom Layer w10: v1(4335,3455) 4320,3470 4320,3473.7 v1(4303.7,3490) 4303.7,3522.97 4342.03,3561.3 4940.71,3561.3 5283.7,3904.29 v1(5283.7,3926.3) ; v1(5605,4348.03) 5635,4348.03 5642.13,4355.16 5642.13,4392.97 5768.31,4519.15 5768.31,4555.91 v1(5768.7,4556.3)
TXD0: FPC2.23 U11.3 | length 2766.5
  Top Layer w10: U11.3 4335,3480.79 v1(4335,3490) ; v1(5315,3920) 5315,3935 5589.17,4209.17 5589.17,4304.8 v1(5610,4325.63) ; FPC2.23 5851.38,4982.64 5874.02,4960 5874.02,4629.02 v1(5785,4540)
  Bottom Layer w10: v1(4335,3490) 4335,3510 4355,3530 4953.67,3530 5315,3891.33 v1(5315,3920) ; v1(5610,4325.63) 5616.42,4332.05 5641.62,4332.05 5658.11,4348.54 5658.11,4386.35 5763.65,4491.89 5776.26,4491.89 5785,4500.63 v1(5785,4540)
VDD_A: C89.1 C92.2 U66.7 | length 240.6
  Bottom Layer w10: C92.2 4827.56,4745 4910,4745 4927.56,4762.56 C89.1 4966.78,4735.78 v1(4989.73,4735.78)
XTI: C103.2 U66.5 X1.1 | length 311.2
  Top Layer w10: X1.1 4806.3,4656.93 4890.42,4656.93 4900,4666.51 4900,4717.56 C103.2 4952.68,4752.56 4972.09,4771.97 4986.55,4771.97 U66.5
XTO: C104.2 U66.4 X1.3 | length 185.7
  Top Layer w10: X1.3 4912.56,4812.72 C104.2 4947.72,4794.84 U66.4
pads on no net: FPC2.13 U65.3 U65.4 U65.5 U65.8 U65.9 U65.10 U65.11 U65.17 U65.19 U66.2 U66.17 U66.18 U66.19 U66.25 U66.28

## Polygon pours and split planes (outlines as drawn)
GND on Bottom Layer (solid, remove dead copper, pour order 2): 3035,4910 6570,4910 6570,3000 3035,3000
GND on Top Layer (solid, remove dead copper, pour order 0): 3000,4920 6400,4920 6400,3075 3000,3075

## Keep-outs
Board Outline Layer:
  lines w10: 5965,5580 5980.9,3270.9 5875,3165 3510,3165 3314.3,3165 3294.5,3184.8 3225,3254.3 3225,3259.4 3235,5538.8 3421.2,5725 3600,5725 5819.7,5725 5965.9,5578.8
